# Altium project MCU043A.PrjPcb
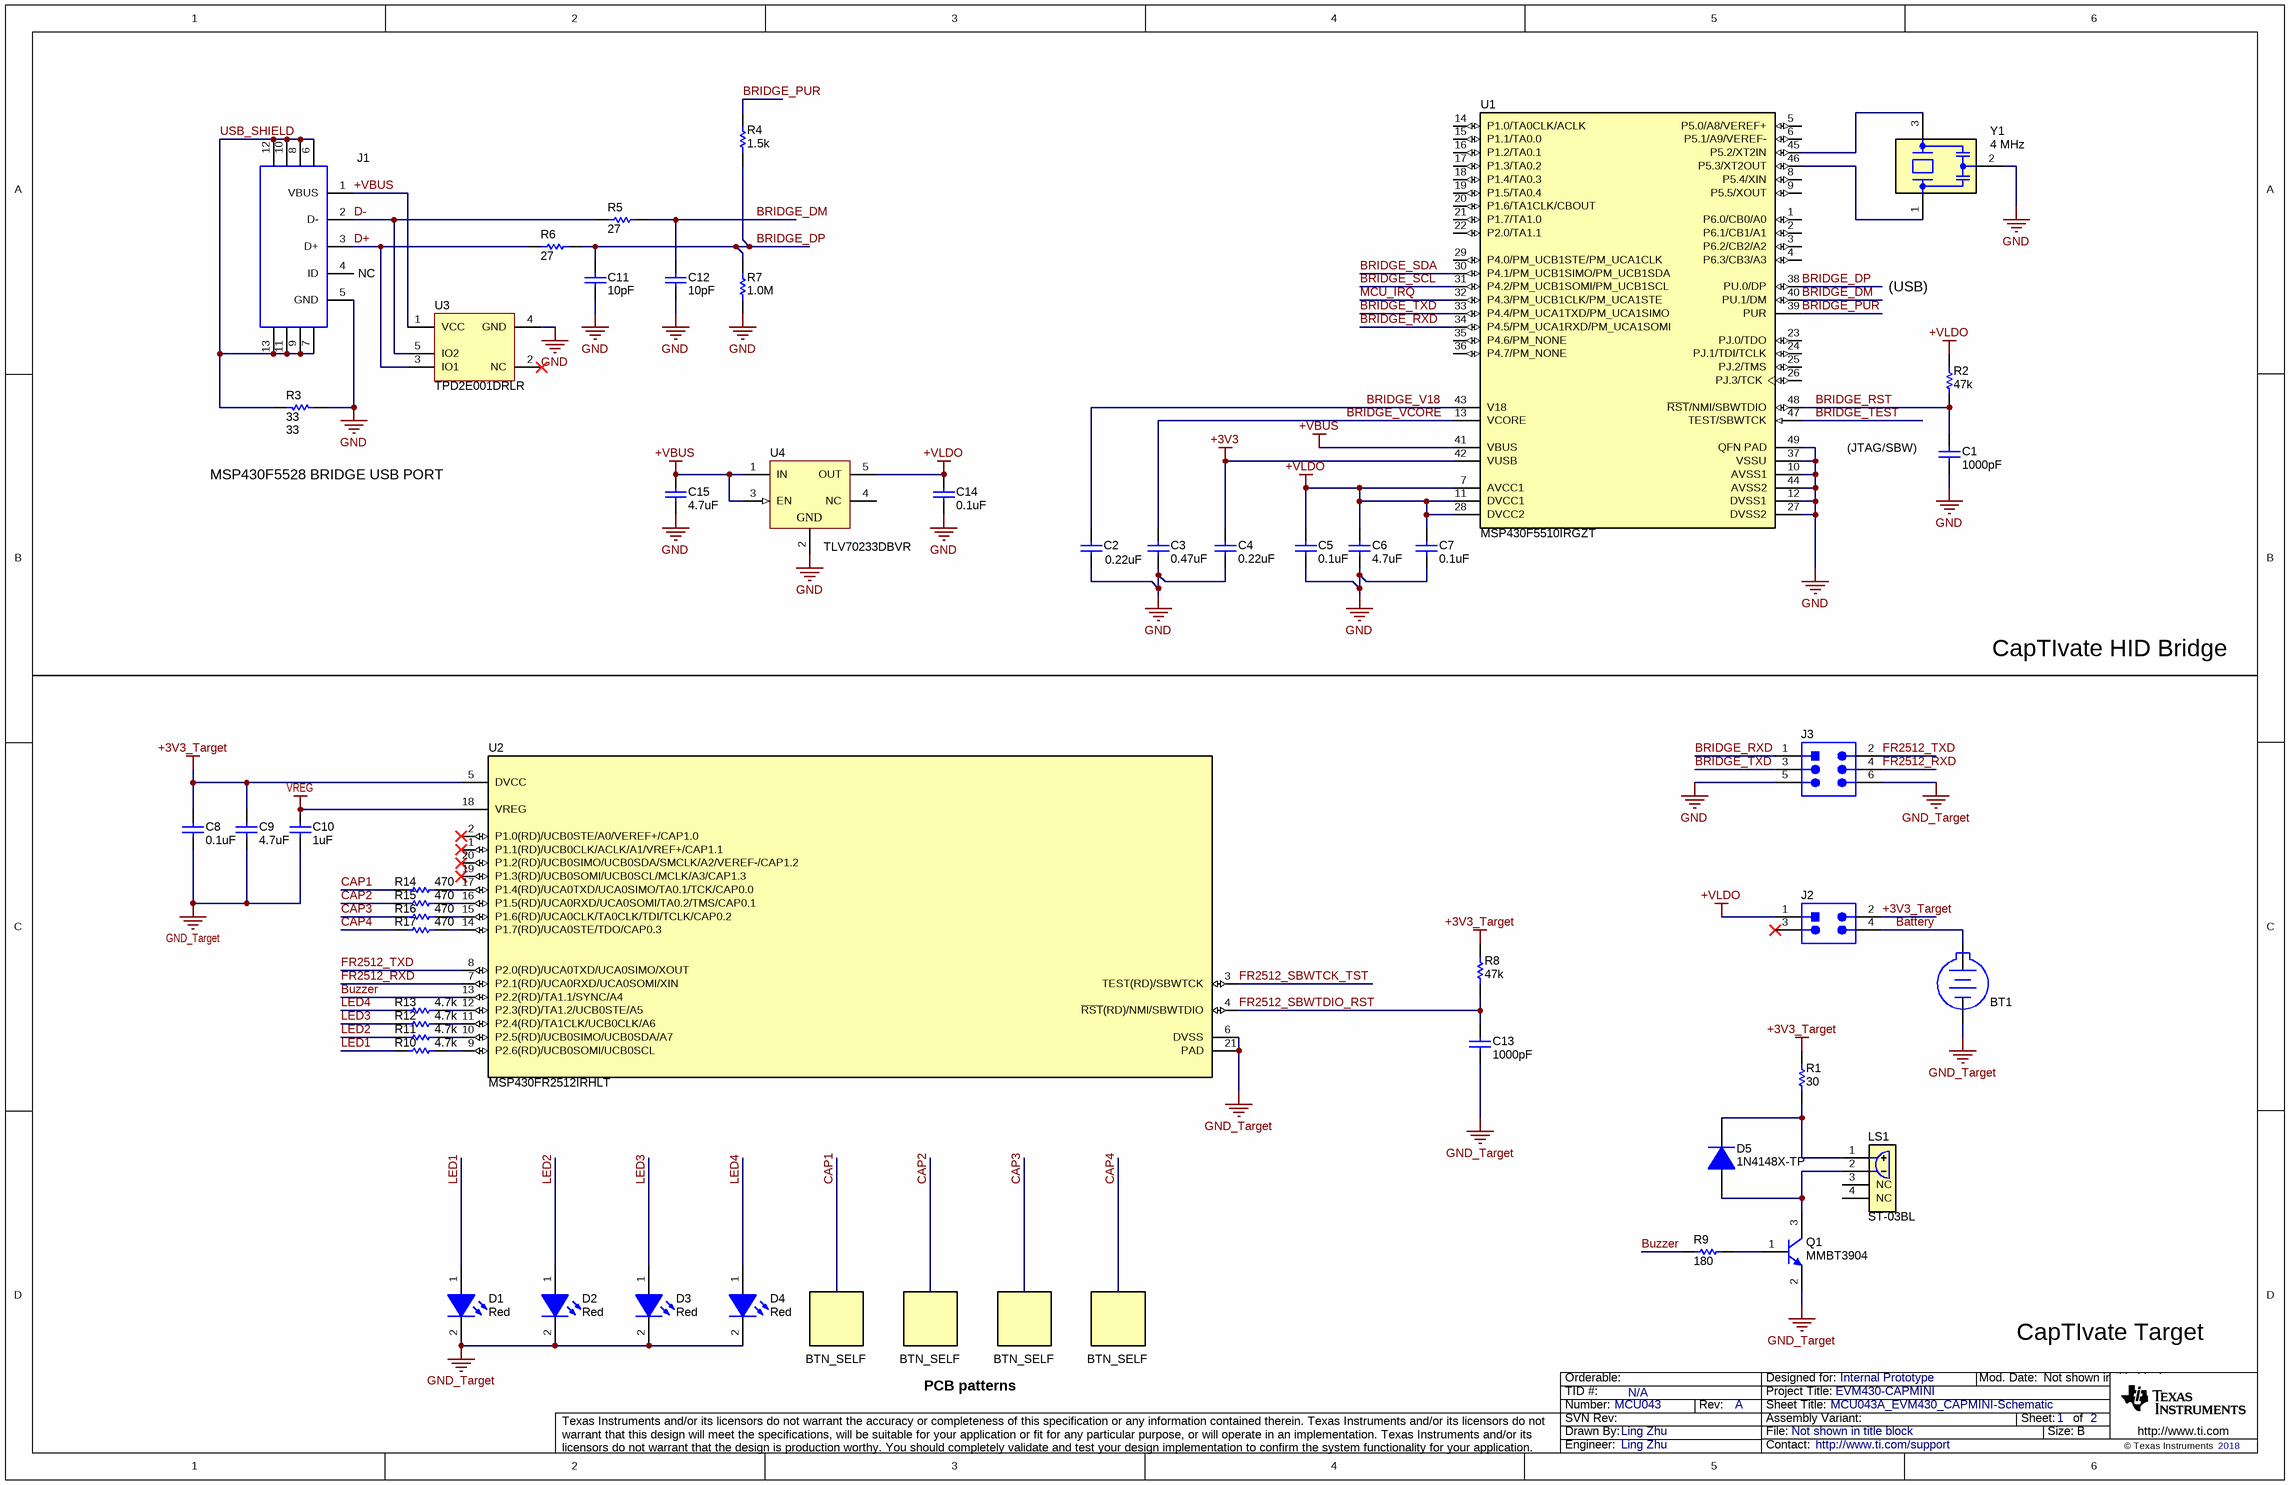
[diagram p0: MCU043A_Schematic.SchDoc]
CopyrightYear: 2018; PCB_Layout: Ling Zhu; PCB_Rev: A; PRJ_Customer: Internal Prototype; PRJ_Engineer: Ling Zhu; PRJ_Number: MCU043; PRJ_Title: EVM430-CAPMINI; SCH_Rev: A; TechSupport: http://www.ti.com/support; TID: N/A
2 sheets, 70 parts. Net scope: global (net labels, ports and power ports of the same name join across sheets).
Board file: MCU043A_PCB.PcbDoc
Sheets:
  MCU043A_Schematic.SchDoc
  MCU043A_Hardware.SchDoc

## Sheet MCU043A_Schematic.SchDoc: MCU043A_EVM430_CAPMINI-Schematic
size 431 x 279 mm; Date: 2017-11-11; ApprovedBy: Not shown in title block; CheckedBy: Not shown in title block; Author: Ling Zhu; CompanyName: Not shown in title block; DrawnBy: Ling Zhu; Engineer: Ling Zhu; Organization: Not shown in title block; Address1: Not shown in title block; Address2: Not shown in title block; Address3: Not shown in title block; Address4: Not shown in title block; DocumentNumber: 1; Revision: .SCH_Rev; SheetNumber: 1; SheetTotal: 2; PageSetup: Record=PageOptions¦CenterHorizontal=True¦CenterVertical=True¦PrintScale=1.00¦XCorrection=1.00¦YCorrection=1.00¦PrintKind=0¦BorderSize=5000000¦LeftOffset=0¦BottomOffset=0¦Orientation=2¦PaperLength=1000¦PaperWidth=1000¦Scale=100¦PaperSource=15¦PrintQuality=600¦MediaType=1¦DitherType=10¦PaperKind=Letter¦PrintScaleMode=1

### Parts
BT1  BU1632SM-JJ-GTR  [MPD_BU1632SM-JJ-GTR]  (value not drawn)
C1  ValueDisplayed: 1000pF  [0402]  (hidden comment: GRM155R61A102KA01D)
C2  ValueDisplayed: 0.22uF  [0402]  (hidden comment: GRM155R61A224KE19D)
C3  ValueDisplayed: 0.47uF  [0402]  (hidden comment: GRM155R61A474KE15D)
C4  ValueDisplayed: 0.22uF  [0402]  (hidden comment: GRM155R61A224KE19D)
C5  ValueDisplayed: 0.1uF  [0402]  (hidden comment: GRM155R61C104KA88D)
C6  ValueDisplayed: 4.7uF  [0603]  (hidden comment: GRM188R61A475MAAJ)
C7  ValueDisplayed: 0.1uF  [0402]  (hidden comment: GRM155R61C104KA88D)
C8  ValueDisplayed: 0.1uF  [0402]  (hidden comment: GRM155R61E104KA87D)
C9  ValueDisplayed: 4.7uF  [0402]  (hidden comment: GRM155R60J475ME87D)
C10  ValueDisplayed: 1uF  [0603]  (hidden comment: GRM185R60J105KE26D)
C11  ValueDisplayed: 10pF  [0402]  (hidden comment: GRM1555C1H100JA01D)
C12  ValueDisplayed: 10pF  [0402]  (hidden comment: GRM1555C1H100JA01D)
C13  ValueDisplayed: 1000pF  [0402]  (hidden comment: GRM155R61A102KA01D)
C14  ValueDisplayed: 0.1uF  [0402]  (hidden comment: GRM155R61C104KA88D)
C15  ValueDisplayed: 4.7uF  [0603]  (hidden comment: GRM188R61A475MAAJ)
D1  value Red  [AM2520_Red]  (hidden comment: AM2520SURCK09)
D2  value Red  [AM2520_Red]  (hidden comment: AM2520SURCK09)
D3  value Red  [AM2520_Red]  (hidden comment: AM2520SURCK09)
D4  value Red  [AM2520_Red]  (hidden comment: AM2520SURCK09)
D5  1N4148X-TP  [SOD-523]
J1  ZX62R-B-5P(30)  [Hirose_ZX62R-B-5P]  (value not drawn)
J2  PBC02DAAN  [Sullins_PxC02DAAN]  (value not drawn)
J3  PBC03DAAN  [Sullins_PBC03DAAN]  (value not drawn)
LS1  ST-03BL  [Soberton_ST-03BL]
Q1  MMBT3904  [SOT-23]
R1  ValueDisplayed: 30  [0402]  (hidden comment: CRCW040230R0JNED)
R2  value 47k  [0402]  (hidden comment: CRCW040247K0JNED)
R3  value 33  [0402]  (hidden comment: CRCW040233R0JNED)
R4  ValueDisplayed: 1.5k  [0402]  (hidden comment: CRCW04021K50JNED)
R5  value 27  [0402]  (hidden comment: CRCW040227R0JNED)
R6  value 27  [0402]  (hidden comment: CRCW040227R0JNED)
R7  ValueDisplayed: 1.0M  [0402]  (hidden comment: CRCW04021M00JNED)
R8  value 47k  [0402]  (hidden comment: CRCW040247K0JNED)
R9  ValueDisplayed: 180  [0402]  (hidden comment: CRCW0402180RJNED)
R10  ValueDisplayed: 4.7k  [0402]  (hidden comment: CRCW04024K70JNED)
R11  ValueDisplayed: 4.7k  [0402]  (hidden comment: CRCW04024K70JNED)
R12  ValueDisplayed: 4.7k  [0402]  (hidden comment: CRCW04024K70JNED)
R13  ValueDisplayed: 4.7k  [0402]  (hidden comment: CRCW04024K70JNED)
R14  ValueDisplayed: 470  [0402]  (hidden comment: CRCW0402470RJNED)
R15  ValueDisplayed: 470  [0402]  (hidden comment: CRCW0402470RJNED)
R16  ValueDisplayed: 470  [0402]  (hidden comment: CRCW0402470RJNED)
R17  ValueDisplayed: 470  [0402]  (hidden comment: CRCW0402470RJNED)
U1  MSP430F5510IRGZT  [RGZ0048A]
U2  MSP430FR2512IRHLT  [RHL0020A]
U3  TPD2E001DRLR  [DRL0005A]
U4  TLV70233DBVR  [DBV0005A_N]
Y1  Frequency_Fixed: 4 MHz  [Murata_CSTCR]  (hidden comment: CSTCR4M00G15L99-R0)

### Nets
+3V3: C4.1 U1.42(VUSB)
+3V3_Target: C8.1 C9.1 J2.2 R1.2 R8.2 U2.5(DVCC)
+VBUS: C15.1 J1.1(VBUS) U1.41(VBUS) U3.1(VCC) U4.1(IN) U4.3(EN)
+VLDO: C5.1 C6.1 C7.1 C14.1 J2.1 R2.2 U1.7(AVCC1) U1.11(DVCC1) U1.28(DVCC2) U4.5(OUT)
GND: C1.2 C2.2 C3.2 C4.2 C5.2 C6.2 C7.2 C11.2 C12.2 C14.2 C15.2 J1.5(GND) J3.5 R3.2 R7.1 U1.10(AVSS1) U1.12(DVSS1) U1.27(DVSS2) U1.37(VSSU) U1.44(AVSS2) U1.49(QFN_PAD) U3.4(GND) U4.2(GND) Y1.2(GND)
GND_Target: BT1.2(-) C8.2 C9.2 C10.2 C13.2 D1.2(K) D2.2(K) D3.2(K) D4.2(K) J3.6 Q1.2(E) U2.6(DVSS) U2.21(PAD)
VREG: C10.1 U2.18(VREG)
Battery: BT1.1(+) J2.4
BRIDGE_DM: C12.1 R5.2 U1.40(PU.1/DM)
BRIDGE_DP: C11.1 R4.1 R6.2 R7.2 U1.38(PU.0/DP)
BRIDGE_PUR: R4.2 U1.39(PUR)
BRIDGE_RST: C1.1 R2.1 U1.48(~{RST}/NMI/SBWTDIO)
BRIDGE_RXD: J3.1 U1.34(P4.5/PM_UCA1RXD/PM_UCA1SOMI)
BRIDGE_SCL: U1.31(P4.2/PM_UCB1SOMI/PM_UCB1SCL)
BRIDGE_SDA: U1.30(P4.1/PM_UCB1SIMO/PM_UCB1SDA)
BRIDGE_TEST: U1.47(TEST/SBWTCK)
BRIDGE_TXD: J3.3 U1.33(P4.4/PM_UCA1TXD/PM_UCA1SIMO)
BRIDGE_V18: C2.1 U1.43(V18)
BRIDGE_VCORE: C3.1 U1.13(VCORE)
Buzzer: R9.1 U2.13(P2.2(RD)/TA1.1/SYNC/A4)
CAP1: R14.1
CAP2: R15.1
CAP3: R16.1
CAP4: R17.1
D+: J1.3(D+) R6.1 U3.3(IO1)
D-: J1.2(D-) R5.1 U3.5(IO2)
FR2512_RXD: J3.4 U2.7(P2.1(RD)/UCA0RXD/UCA0SOMI/XIN)
FR2512_SBWTCK_TST: U2.3(TEST(RD)/SBWTCK)
FR2512_SBWTDIO_RST: C13.1 R8.1 U2.4(~{RST}(RD)/NMI/SBWTDIO)
FR2512_TXD: J3.2 U2.8(P2.0(RD)/UCA0TXD/UCA0SIMO/XOUT)
LED1: D1.1(A) R10.1
LED2: D2.1(A) R11.1
LED3: D3.1(A) R12.1
LED4: D4.1(A) R13.1
MCU_IRQ: U1.32(P4.3/PM_UCB1CLK/PM_UCA1STE)
USB_SHIELD: J1.6 J1.7 J1.8 J1.9 J1.10 J1.11 J1.12 J1.13 R3.1
NetD5_1: D5.1(K) LS1.1(+) R1.1
NetD5_2: D5.2(A) LS1.2(-) Q1.3(C)
NetQ1_1: Q1.1(B) R9.2
NetR10_2: R10.2 U2.9(P2.6(RD)/UCB0SOMI/UCB0SCL)
NetR11_2: R11.2 U2.10(P2.5(RD)/UCB0SIMO/UCB0SDA/A7)
NetR12_2: R12.2 U2.11(P2.4(RD)/TA1CLK/UCB0CLK/A6)
NetR13_2: R13.2 U2.12(P2.3(RD)/TA1.2/UCB0STE/A5)
NetR14_2: R14.2 U2.17(P1.4(RD)/UCA0TXD/UCA0SIMO/TA0.1/TCK/CAP0.0)
NetR15_2: R15.2 U2.16(P1.5(RD)/UCA0RXD/UCA0SOMI/TA0.2/TMS/CAP0.1)
NetR16_2: R16.2 U2.15(P1.6(RD)/UCA0CLK/TA0CLK/TDI/TCLK/CAP0.2)
NetR17_2: R17.2 U2.14(P1.7(RD)/UCA0STE/TDO/CAP0.3)
NetU1_45: U1.45(P5.2/XT2IN) Y1.3(Out)
NetU1_46: U1.46(P5.3/XT2OUT) Y1.1(In)

Not connected (* = marked no-connect by the designer): J1 4(ID); J2 3*; LS1 3(NC) 4(NC); U1 1(P6.0/CB0/A0) 2(P6.1/CB1/A1) 3(P6.2/CB2/A2) 4(P6.3/CB3/A3) 5(P5.0/A8/VEREF+) 6(P5.1/A9/VEREF-) 8(P5.4/XIN) 9(P5.5/XOUT) 14(P1.0/TA0CLK/ACLK) 15(P1.1/TA0.0) 16(P1.2/TA0.1) 17(P1.3/TA0.2) 18(P1.4/TA0.3) 19(P1.5/TA0.4) 20(P1.6/TA1CLK/CBOUT) 21(P1.7/TA1.0) 22(P2.0/TA1.1) 23(PJ.0/TDO) 24(PJ.1/TDI/TCLK) 25(PJ.2/TMS) 26(PJ.3/TCK) 29(P4.0/PM_UCB1STE/PM_UCA1CLK) 35(P4.6/PM_NONE) 36(P4.7/PM_NONE); U2 1(P1.1(RD)/UCB0CLK/ACLK/A1/VREF+/CAP1.1)* 2(P1.0(RD)/UCB0STE/A0/VEREF+/CAP1.0)* 19(P1.3(RD)/UCB0SOMI/UCB0SCL/MCLK/A3/CAP1.3)* 20(P1.2(RD)/UCB0SIMO/UCB0SDA/SMCLK/A2/VEREF-/CAP1.2)*; U3 2(NC)*; U4 4(NC)

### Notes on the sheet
- (near J1) NC
- (USB)
- MSP430F5528 BRIDGE USB PORT
- (near C1) (JTAG/SBW)
- CapTIvate HID Bridge
- BTN_SELF
- CapTIvate Target
- PCB patterns

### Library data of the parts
BT1 = CMP-0078509-1: HOLDER COIN CELL 1632 GOLD, SMD; Manufacturer: Memory Protection Devices; CompType: Battery Holder
C1 C13 = GRM155R61A102KA01D: CAP, CERM, 1000 pF, 10 V,+/- 10%, X5R, 0402; Manufacturer: MuRata; Polarized: N; CompType: Capacitor; Value: 1000pF; U/M: EA; Cap_F: 0.000000001; Tolerance_%: 10; Value2: 10V; TaMin_C: -55; TaMax_C: 85; SizeArea_mm2: 0.5; SizeAreaWB_mm2: 3; SizeX_mm: 1; SizeZ_mm: 0.6; AEC Category: Q200; Green_Lifecycle: Active; Green_REACh: Passed
C2 = CMP-0006570-2: CAP, CERM, 0.22 uF, 10 V, +/- 10%, X5R, 0402; Manufacturer: MuRata; TaMin_C: -55°C; Polarized: N; SizeAreaWB_mm2: 3; Value1: Unknown; U/M: EA; Value: 0.22uF; TaMax_C: 85°C; SizeZ_mm: 0.6; SizeX_mm: 1; SizeY_mm: 0.5; Value2: 10V; Cap_F: 220nF; AEC Category: Q200
C3 = CMP-0006580-2: CAP, CERM, 0.47 uF, 10 V, +/- 10%, X5R, 0402; Manufacturer: MuRata; TaMin_C: -55°C; Polarized: N; SizeAreaWB_mm2: 3; Value1: Unknown; U/M: EA; Value: 0.47uF; TaMax_C: 85°C; SizeZ_mm: 0.6; SizeX_mm: 1; SizeY_mm: 0.5; Value2: 10V; CompType: Capacitor; Cap_F: 470nF; AEC Category: Q200
C4 = CMP-0006570-2: CAP, CERM, 0.22 uF, 10 V, +/- 10%, X5R, 0402; Manufacturer: MuRata; TaMin_C: -55°C; Polarized: N; SizeAreaWB_mm2: 3; Value1: Unknown; U/M: EA; Value: 0.22uF; TaMax_C: 85°C; SizeZ_mm: 0.6; SizeX_mm: 1; SizeY_mm: 0.5; Value2: 10V; CompType: Capacitor; Cap_F: 220nF; AEC Category: Q200
C5 C7 C14 = CMP-0006591-2: CAP, CERM, 0.1 uF, 16 V, +/- 10%, X5R, 0402; Manufacturer: MuRata; TaMin_C: -55°C; Polarized: N; SizeAreaWB_mm2: 3; Value1: Unknown; U/M: EA; Value: 0.1uF; TaMax_C: 85°C; SizeZ_mm: 0.6; SizeX_mm: 1; SizeY_mm: 0.5; Value2: 16V; Cap_F: 100nF; AEC Category: Q200
C6 C15 = CMP-0007329-5: CAP, CERM, 4.7 uF, 10 V, +/- 20%, X5R, 0603; Manufacturer: MuRata; TaMin_C: -55°C; Polarized: N; SizeAreaWB_mm2: 4.68; Value1: Unknown; U/M: EA; Value: 4.7uF; TaMax_C: 85°C; SizeZ_mm: 1; SizeX_mm: 1.6; SizeY_mm: 0.8; Value2: 10V; SizeArea_mm2: 1.28; Cap_F: 4.7µF; AEC Category: Q200
C8 = CMP-0006607-2: CAP, CERM, 0.1 uF, 25 V, +/- 10%, X5R, 0402; Manufacturer: MuRata; TaMin_C: -55°C; Polarized: N; SizeAreaWB_mm2: 3; Value1: Unknown; U/M: EA; Value: 0.1uF; TaMax_C: 85°C; SizeZ_mm: 0.6; SizeX_mm: 1; SizeY_mm: 0.5; Value2: 25V; Cap_F: 100nF; AEC Category: Q200
C9 = CMP-0006553-2: CAP, CERM, 4.7 uF, 6.3 V, +/- 20%, X5R, 0402; Manufacturer: MuRata; TaMin_C: -55°C; ESR_ohm: 9m; Polarized: N; SizeAreaWB_mm2: 3; Value1: 0.009 ohm; U/M: EA; Value: 4.7uF; TaMax_C: 85°C; SizeZ_mm: 0.6; SizeX_mm: 1; SizeY_mm: 0.5; Cap_F: 4.7µF; VDC_V: 6.3V; IRMS_A: 1.22A; AEC Category: Q200
C10 = CMP-0007155-5: CAP, CERM, 1 uF, 6.3 V, +/- 10%, X5R, 0603; Manufacturer: MuRata; TaMin_C: -55°C; Polarized: N; SizeAreaWB_mm2: 4.68; Value1: Unknown; U/M: EA; Value: 1uF; TaMax_C: 85°C; SizeZ_mm: 1; SizeX_mm: 1.6; SizeY_mm: 0.8; Value2: 6.3V; SizeArea_mm2: 1.28; Cap_F: 1µF; AEC Category: Q200
C11 C12 = GRM1555C1H100JA01D: CAP, CERM, 10pF, 50V, +/-5%, C0G/NP0, 0402; Manufacturer: MuRata; Polarized: N; CompType: Capacitor; U/M: EA; Cap_F: 0.00000000001; Tolerance_%: 5; Value1: Unknown; VDC_V: 50; TaMin_C: -55; TaMax_C: 125
D1-D4 = AM2520SURCK09: LED, Red, SMD; Manufacturer: Kingbright; Type: AlInGaP; Vf_V: 1.95; Value2: 1.95V; Io_A: 0.02; Vr_V: 5; Ir_A: 1e-005; Tjmax_C: 85; Power_TotalModule: 0.075; Value1: 0.075W; Angle: 20; SizeAreaWB_mm2: 31.2; SizeArea_mm2: 11.6; SizeX_mm: 5.8; SizeY_mm: 2; SizeZ_mm: 1.5; U/M: EA
D5 = CMP-0076957-2: Diode, Switching, 75 V, 0.3 A, SOD-523; Manufacturer: Micro Commercial Components; SizeAreaWB_mm2: 5.13; Vr_V: 75V; SizeArea_mm2: 1.53; TJmax_C: 150°C; AEC Category: Q101; Value: 75V; SizeZ_mm: 0.65; Green_REACh: Incomplete; Io_A: 3dA; Vf_V: 1.25V; SizeY_mm: 0.9; Green_Lifecycle: Not Set; U/M: EA; Value1: 0.3A; SizeX_mm: 1.7
J1 = CMP-0079906-1: Connector, Receptacle, Micro-USB Type B, Top Mount SMT; Manufacturer: Hirose Electric Co. Ltd.; Current_A: 1.8A; Gender: Female; Voltage_V: 30V; CompType: USB; ContactFinish: Gold
J2 = CMP-0054598-1: Header, 2.54mm, 2x2, Gold, TH; Manufacturer: Sullins Connector Solutions; CNHeader: TRUE; Current_A: 3A; Shrouded: N; Gender: Male; Voltage_V: 1.8kV; Row_Count: 2; RowSpacing_mm: 2.54; CT: FALSE; Cert_UL: Y
J3 = CMP-0054565-1: Header, 100mil, 3x2, Gold, TH; Manufacturer: Sullins Connector Solutions; CNHeader: TRUE; Current_A: 3A; Green_Lifecycle: Active; Shrouded: N; Gender: Male; Green_REACh: Passed; Voltage_V: 1.8kV; Row_Count: 2; RowSpacing_mm: 2.54; CT: FALSE; Cert_UL: Y
LS1 = CMP-0078858-1: Magnetic Transducer, SMD; Manufacturer: Sobertron; SizeArea_mm2: 72.25; SizeAreaWB_mm2: 110.25; SizeY_mm: 8.5; SizeZ_mm: 3.2
Q1 = MMBT3904, Fairchild Semiconductor: Transistor, NPN, 40 V, 0.2 A, SOT-23; CompType: BJT; PNP: 0; NPN: 1; Vceo_V: 40; Vcesat1_V: 0.2; Value: 40 V; Value1: 0.2 A; HfeMax: 300; TaMin_C: -55; TaMax_C: 150; SizeAreaWB_mm2: 14; SizeArea_mm2: 7.5; SizeX_mm: 2.5; SizeY_mm: 3; SizeZ_mm: 1.1; U/M: EA; AEC Category: Q101; Green_Lifecycle: Active; Green_REACh: Passed
R1 = CMP-0026904-3: RES, 30, 5%, 0.063 W, AEC-Q200 Grade 0, 0402; Manufacturer: Vishay-Dale; Power_W: 63mW; TempCo: 200 ppm/C; Value_Code: 30R0; Value: 30; EIA_Code: E24; SizeX_mm: 1; SizeY_mm: 0.5; SizeZ_mm: 0.6; Value2: 0.063W; CompType: Resistor; AEC Qualified: Y; VDC_V: 50V; AEC Category: Q200; AEC Grade: 0
R2 R8 = CRCW040247K0JNED: RES, 47k ohm, 5%, 0.063W, 0402; Manufacturer: Vishay-Dale; CompType: Resistor; Res_ohm: 47000; Value_Code: 47k0; Tolerance_%: 5; Power_W: 0.063; VDC_V: 50; TempCo: 200 ppm/C; EIA_Code: E24; U/M: EA
R3 = CRCW040233R0JNED: RES, 33, 5%, 0.063 W, 0402; Manufacturer: Vishay-Dale; CompType: Resistor; Value_Code: 33R0; Tolerance_%: 5; Power_W: 0.063; Value2: 0.063W; VDC_V: 50; TempCo: 200 ppm/C; EIA_Code: E24; U/M: EA; SizeArea_mm2: 0.5; SizeX_mm: 1; SizeZ_mm: 0.6; AEC Category: Q200
R4 = CRCW04021K50JNED: RES, 1.5 k, 5%, 0.063 W, 0402; Manufacturer: Vishay-Dale; CompType: Resistor; Value: 1.5k; Res_ohm: 1500; Value_Code: 1k50; Tolerance_%: 5; Power_W: 0.063; Value2: 0.063W; VDC_V: 50; TempCo: 200 ppm/C; SizeArea_mm2: 0.5; SizeX_mm: 1; SizeZ_mm: 0.6; EIA_Code: E24; U/M: EA; AEC Category: Q200; Green_Lifecycle: Active; Green_REACh: Passed
R5 R6 = CRCW040227R0JNED: RES, 27 ohm, 5%, 0.063W, 0402; Manufacturer: Vishay-Dale; CompType: Resistor; Value_Code: 27R0; Tolerance_%: 5; Power_W: 0.063; VDC_V: 50; TempCo: 200 ppm/C; EIA_Code: E24; U/M: EA
R7 = CRCW04021M00JNED: RES, 1.0 M, 5%, 0.063 W, 0402; Manufacturer: Vishay-Dale; CompType: Resistor; Value: 1.0Meg; Res_ohm: 1000000; Value_Code: 1M00; Tolerance_%: 5; Power_W: 0.063; Value2: 0.063W; VDC_V: 50; TempCo: 200 ppm/C; SizeArea_mm2: 0.5; SizeX_mm: 1; SizeZ_mm: 0.6; EIA_Code: E24; U/M: EA; AEC Category: Q200; Green_Lifecycle: Active; Green_REACh: Passed
R9 = CRCW0402180RJNED: RES, 180, 5%, 0.063 W, 0402; Manufacturer: Vishay-Dale; CompType: Resistor; Value: 180; Value_Code: 180R; Tolerance_%: 5; Power_W: 0.063; Value2: 0.063W; VDC_V: 50; TempCo: 200 ppm/C; SizeArea_mm2: 0.5; SizeX_mm: 1; SizeZ_mm: 0.6; EIA_Code: E24; U/M: EA; AEC Category: Q200; Green_Lifecycle: Active; Green_REACh: Passed
R10-R13 = CMP-0026938-5: RES, 4.7 k, 5%, 0.063 W, AEC-Q200 Grade 0, 0402; Manufacturer: Vishay-Dale; Power_W: 63mW; TempCo: 200 ppm/C; Value_Code: 4k70; Value: 4.7k; EIA_Code: E24; SizeX_mm: 1; SizeY_mm: 0.5; SizeZ_mm: 0.6; Value2: 0.063W; AEC Qualified: Y; VDC_V: 50V; AEC Category: Q200; AEC Grade: 0
R14-R17 = CRCW0402470RJNED: RES, 470, 5%, 0.063 W, 0402; Manufacturer: Vishay-Dale; CompType: Resistor; Value: 470; Value_Code: 470R; Tolerance_%: 5; Power_W: 0.063; Value2: 0.063W; VDC_V: 50; TempCo: 200 ppm/C; SizeArea_mm2: 0.5; SizeX_mm: 1; SizeZ_mm: 0.6; EIA_Code: E24; U/M: EA; AEC Category: Q200; Green_Lifecycle: Active; Green_REACh: Passed
U1 = MSP430F5510IRGZT: 25 MHz Mixed Signal Microcontroller with 32 KB Flash, 4096 B SRAM and 47 GPIOs, -40 to 85 degC, 48-pin QFN (RGC), Green (RoHS & no Sb/Br); Alternate Manufacturer: Texas Instruments; Alternate PartNumber: Equivalent; ADC: 10-bit SAR; ADC Channels: 8; Brown Out Reset: Yes; DMA: 3; Flash(KB): 32; Frequency(MHz): 25; GPIO: 47; Multiplier: 32x32; Pin/Package: 48LQFP, 64VQFN, 48VQFN, 80BGA MICROSTAR JUNIOR; SRAM(B): 4096; SubFamily: 5 Series; Timers - 16-bit: 4; USB: 1; USCI_A (UART/LIN/IrDA/SPI): 2
U2 = CMP-0078346-1: Capacitive Touch Sensing Mixed-Signal Microcontroller, RHL0020A (VQFN-20); Alternate PartNumber: MSP430FR2512IRHLR; Alternate Manufacturer: Texas Instruments; SizeAreaWB_mm2: 24.75; SizeZ_mm: 1; SizeX_mm: 4.5; SizeY_mm: 3.5; SizeArea_mm2: 15.75; CompType: IC; AEC Qualified: N; AEC Category: Q200
U3 = TPD2E001DRLR: Low-Capacitance + / - 15 kV ESD-Protection Array for High-Speed Data Interfaces, 2 Channels, -40 to +85 degC, 5-pin SOT (DRL), Green (RoHS & no Sb/Br); Manufacturer: Texas Instruments; Alternate Manufacturer: None; Alternate PartNumber: Equivalent; Breakdown Voltage(Min)(V): 11; IEC 61000-4-2 Air-Gap(+/- kV): 15; IEC 61000-4-2 Contact(+/- kV): 8; IO Capacitance(Typ)(pF): 1.5; IO Leakage Current(nA): 1; SubFamily: ESD Solution; USB High Speed: TRUE
U4 = CMP-0035516-1: Single Output LDO, 300 mA, Fixed 3.3 V Output, 2 to 5.5 V Input, with Low IQ, 5-pin SOT-23 (DBV), -40 to 125 degC, Green (RoHS & no Sb/Br); Manufacturer: Texas Instruments; Fixed Output Options(V): 3.3; Vdo(Typ)(mV): 220; Accuracy(%): 2; Iq(Typ)(mA): 0.03; SubFamily: Single Channel LDO; Iout(Max)(A): 0.3; Vin(Max)(V): 5.5
Y1 = CSTCR4M00G15L99-R0: Resonator, 4 MHz, 39pF SMD; Manufacturer: MuRata; SymbolCreator: a0799721; U/M: EA; TaMin_C: 0; TaMax_C: 70; Frequency Stability: ±0.08 %; Green_Lifecycle: Not Set; Green_REACh: Incomplete

## Sheet MCU043A_Hardware.SchDoc: MCU043A_EVM430_CAPMINI-Hardware
size 431 x 279 mm; Date: Not shown in title block; ApprovedBy: Not shown in title block; CheckedBy: Not shown in title block; Author: Not shown in title block; CompanyName: Not shown in title block; DrawnBy: Ling Zhu; Engineer: Ling Zhu; Organization: Not shown in title block; Address1: Not shown in title block; Address2: Not shown in title block; Address3: Not shown in title block; Address4: Not shown in title block; DocumentNumber: 1; Revision: .SCH_Rev; SheetNumber: 2; SheetTotal: 2; PageSetup: Record=PageOptions¦CenterHorizontal=True¦CenterVertical=True¦PrintScale=1.00¦XCorrection=1.00¦YCorrection=1.00¦PrintKind=0¦BorderSize=5000000¦LeftOffset=0¦BottomOffset=0¦Orientation=2¦PaperLength=1000¦PaperWidth=1000¦Scale=100¦PaperSource=15¦PrintQuality=600¦MediaType=1¦DitherType=10¦PaperKind=Letter¦PrintScaleMode=1
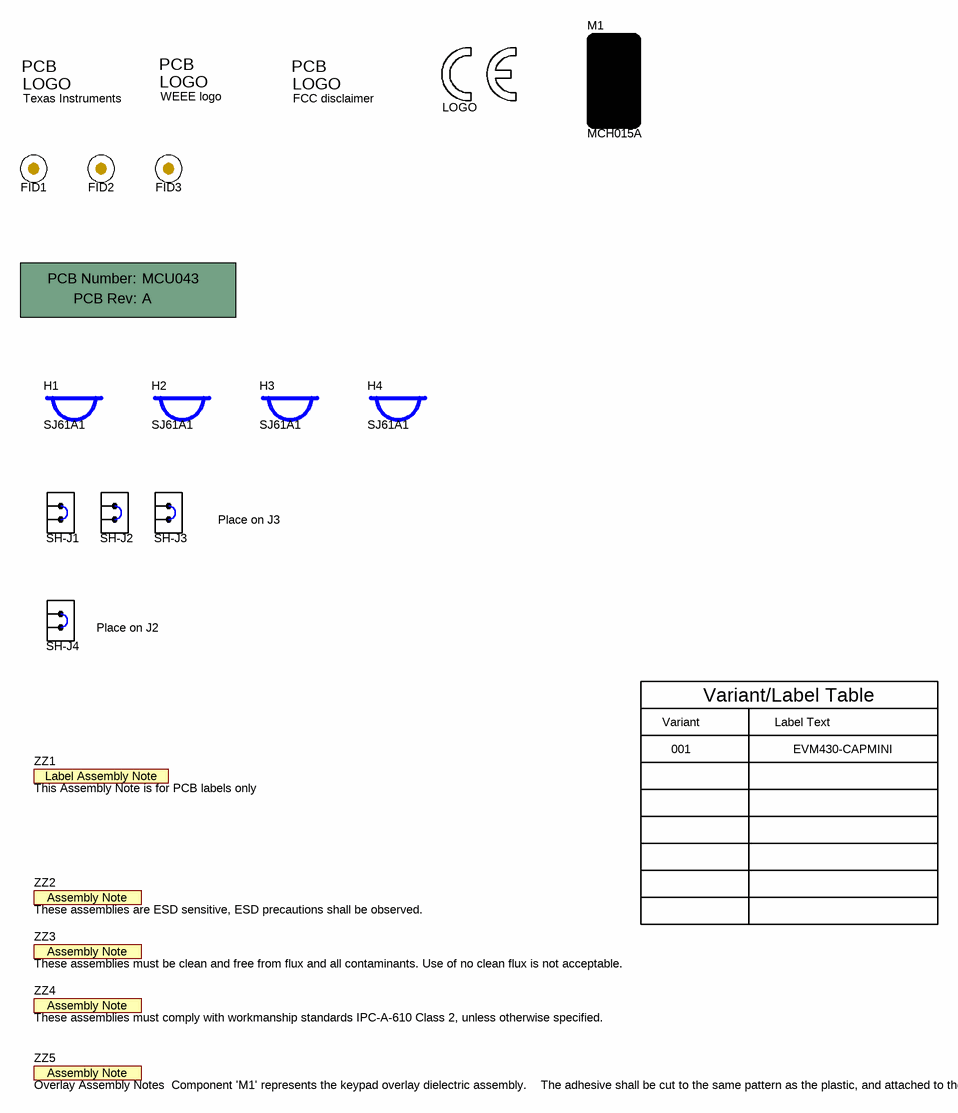
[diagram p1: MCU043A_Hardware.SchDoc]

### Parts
!PCB1  Printed Circuit Board  (value not drawn)  (mechanical)
FID1  Fiducial  [Fiducial10-20]  (value not drawn)
FID2  Fiducial  [Fiducial10-20]  (value not drawn)
FID3  Fiducial  [Fiducial10-20]  (value not drawn)
H1  SJ61A1  [Bumpon_SJ61A1]
H2  SJ61A1  [Bumpon_SJ61A1]
H3  SJ61A1  [Bumpon_SJ61A1]
H4  SJ61A1  [Bumpon_SJ61A1]
LOGO  CE Mark  [CE_Mark_5mm]  (value not drawn)  (no BOM)
Logo1  Texas Instruments  [TI_Stacked_Overlay_Small]  (no BOM)
Logo2  WEEE logo  [WEEE_Minimum]  (no BOM)
Logo3  FCC disclaimer  [FCC_disclaimer]  (no BOM)
M1  MCH015A  [EVM430-CAPMINI-OVERLAY-PMMA]
SH-J1  SPC02SYAN  [SPC02SYAN]  (value not drawn)
SH-J2  SPC02SYAN  [SPC02SYAN]  (value not drawn)
SH-J3  SPC02SYAN  [SPC02SYAN]  (value not drawn)
SH-J4  SPC02SYAN  [SPC02SYAN]  (value not drawn)
ZZ1  This Assembly Note is for PCB labels only  [AssemblyNoteLabel]  (no BOM)
ZZ2  These assemblies are ESD sensitive, ESD precautions shall be observed.  [AssemblyNote]  (no BOM)
ZZ3  These assemblies must be clean and free from flux and all contaminants. Use of no clean flux is not acceptable.  [AssemblyNote]  (no BOM)
ZZ4  These assemblies must comply with workmanship standards IPC-A-610 Class 2, unless otherwise specified.  [AssemblyNote]  (no BOM)
ZZ5  Overlay Assembly Notes  Component 'M1' represents the keypad overlay dielectric assembly.    The adhesive shall be cut to the same pattern as the plastic, and attached to the back of the plastic.  Then, the overlay plastic shall be bonded to the bottom layer of the PCB.     For a detailed drawing of the overlay, see MCH015A_Mech.pdf  [AssemblyNote]  (no BOM)

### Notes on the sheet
- (near SH-J3) Place on J3
- (near SH-J4) Place on J2
- Variant
- Variant/Label Table
- Label Text
- 001
- EVM430-CAPMINI

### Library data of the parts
!PCB1 = PCB: Manufacturer: Any; PartNumber: MCU043; SymbolCreator: a0412235
FID1-FID3 = Fiducial: Fiducial mark.  There is nothing to buy or mount.; SymbolCreator: codlsc
H1-H4 = SJ61A1: Bumpon, Cylindrical, 0.312 X 0.200, Black; Manufacturer: 3M; SymbolCreator: a0412235
LOGO = CE Mark: SymbolCreator: a0412235
Logo1 = TI_Logo: Texas Instrument Corporate Signature; SymbolCreator: codlsc
Logo2 = CMP-0074769-1
Logo3 = FCC_disclaimer: SymbolCreator: codlsc
M1 = EVM430-CAPMINI-OVERLAY-PMMA: EVM430-CAPMINI Overlay Plastic; SymbolCreator: a0222632; CompType: Mechanical; U/M: EA, IN, or GM
SH-J1-SH-J4 = SPC02SYAN: Shunt, 100mil, Flash Gold, Black; Manufacturer: Sullins Connector Solutions; Value: 1x2; Note: You can "mate" this to a header by matching the designator.  i.e. use SH-J3 for header J3; Green_Lifecycle: Active; Green_REACh: Passed
ZZ1 = AssemblyNoteLabel: SymbolCreator: a0412235
ZZ2-ZZ5 = AssemblyNote: SymbolCreator: codlsc

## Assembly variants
001: not fitted FID1 FID2 FID3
